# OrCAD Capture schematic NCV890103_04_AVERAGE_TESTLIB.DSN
size A
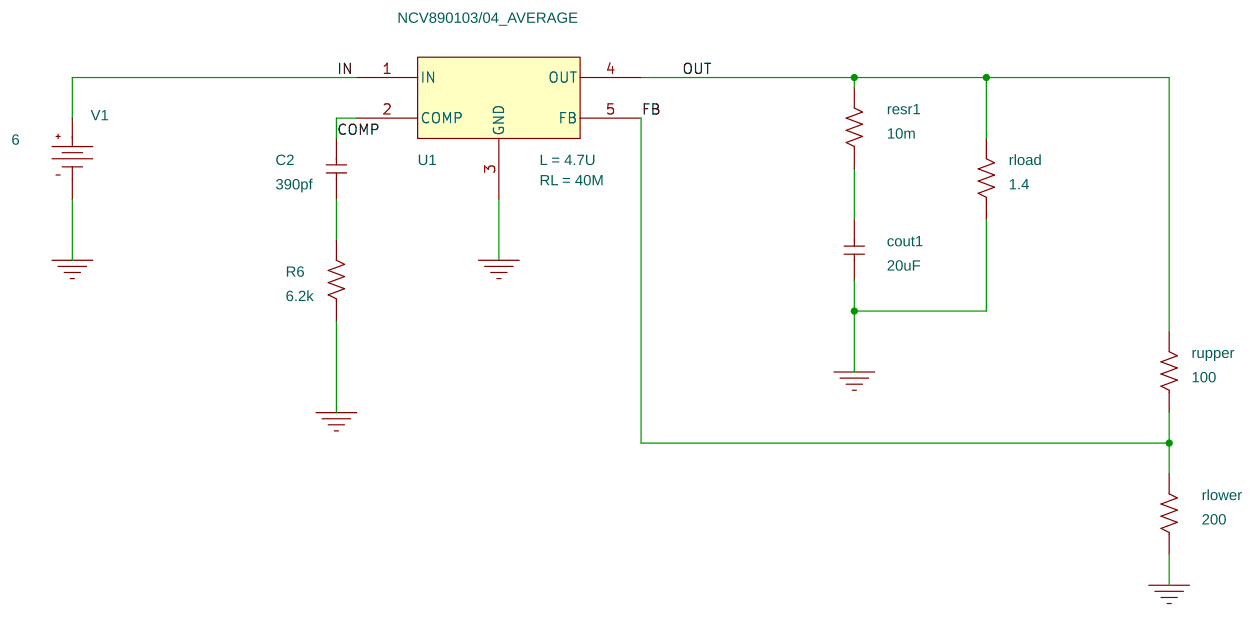
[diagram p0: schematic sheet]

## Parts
C2  390pf  [RAD/CK05]
cout1  20uF  [RAD/CK05]
R6  6.2k  [AX/RC05]
resr1  10m  [AX/RC05]
rload  1.4  [AX/RC05]
rlower  200  [AX/RC05]
rupper  100  [AX/RC05]
U1  NCV890103/04_AVERAGE
V1  VDC

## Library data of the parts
C2 cout1 = C
R6 resr1 rload rlower rupper = R
U1 = NCV8901XX_AVERAGE: L: 4.7U; RL: 40M
V1 = VDC: DC: 6

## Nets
0: cout1.1 R6.1 rload.1 rlower.1 U1.3(GND) V1.1(-)
COMP: C2.2 U1.2(COMP)
FB: rlower.2 rupper.1 U1.5(FB)
IN: U1.1(IN) V1.0(+)
OUT: resr1.2 rload.2 rupper.2 U1.4(OUT)
N7610953: cout1.2 resr1.1
N7611007: C2.1 R6.2
